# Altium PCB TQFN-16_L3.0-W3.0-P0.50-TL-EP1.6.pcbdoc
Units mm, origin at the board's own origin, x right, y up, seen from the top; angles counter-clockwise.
Board outline 16.98 x 16.5 mm, 2 copper layers (Top Layer, Bottom Layer), stack 0 mm thick; 1 components, 0 nets, 17 pads, 0 vias.
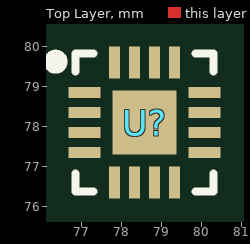
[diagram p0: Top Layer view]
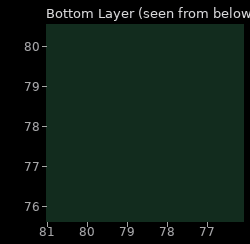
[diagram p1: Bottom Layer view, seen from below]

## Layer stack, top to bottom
Top Layer: signal copper (thickness not stored)
Bottom Layer: signal copper (thickness not stored)

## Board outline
86.825,69.85 69.85,69.85 69.85,86.35 86.825,86.35

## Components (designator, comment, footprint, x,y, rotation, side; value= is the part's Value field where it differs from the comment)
U? "" TQFN-16_L3.0-W3.0-P0.50-TL-EP1.6 78.575,78.1 r0 top

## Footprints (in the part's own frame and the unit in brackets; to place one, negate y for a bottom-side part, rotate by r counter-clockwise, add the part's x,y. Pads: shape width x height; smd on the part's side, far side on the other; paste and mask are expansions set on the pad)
TQFN-16_L3.0-W3.0-P0.50-TL-EP1.6 [mm]
  rect 0.8x0.28 smd paste-100 mask+0.05: 1(-1.5,0.749) 2(-1.5,0.249) 3(-1.5,-0.249) 4(-1.5,-0.749) 9(1.5,-0.749) 10(1.5,-0.249) 11(1.5,0.249) 12(1.5,0.749)
  rect 0.28x0.8 smd paste-100 mask+0.05: 5(-0.749,-1.5) 6(-0.249,-1.5) 7(0.249,-1.5) 8(0.749,-1.5) 13(0.749,1.5) 14(0.249,1.5) 15(-0.249,1.5) 16(-0.749,1.5)
  rect 1.6x1.6 smd paste-100 mask+0.05: 17(0,0)
  silkscreen extent -2.38,-1.72 1.72,1.72

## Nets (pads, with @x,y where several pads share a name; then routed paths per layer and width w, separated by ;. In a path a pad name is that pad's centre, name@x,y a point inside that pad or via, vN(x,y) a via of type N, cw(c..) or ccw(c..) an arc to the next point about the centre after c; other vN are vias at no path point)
pads on no net: U?.1 U?.2 U?.3 U?.4 U?.5 U?.6 U?.7 U?.8 U?.9 U?.10 U?.11 U?.12 U?.13 U?.14 U?.15 U?.16 U?.17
